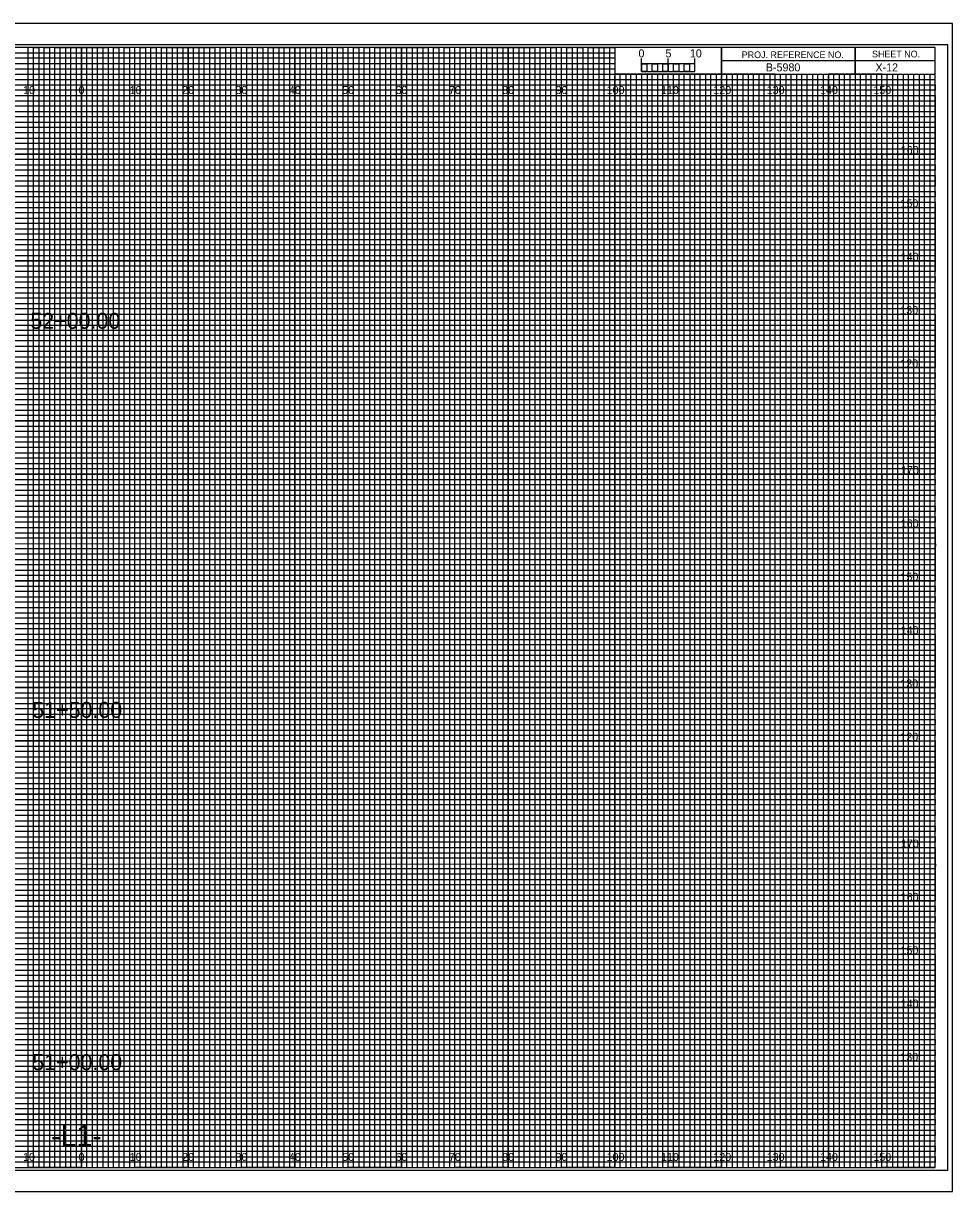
# Model space of a CAD drawing. Extents: x -13 to 323, y -5 to 3294.
# Drawn here: x 149.1 to 323.3, y 2415.5 to 2634.5 of the extents above; entities that cross this region are included whole.
import ezdxf

# ---------------------------------------------------------------- set-up
doc = ezdxf.new("R2010")
doc.units = 0
for name, color, linetype in [('Prop XS Alignment Label', 7, 'Continuous'), ('Prop XS Bar Scale Labels', 7, 'Continuous'), ('Prop XS Elevation Labels', 7, 'Continuous'), ('Prop XS Offset Labels', 7, 'Continuous'), ('Prop XS Project Number', 7, 'Continuous'), ('Prop XS Sheet Number', 7, 'Continuous'), ('Prop XS Station Labels', 7, 'Continuous'), ('Scratch_Level_0', 7, 'Continuous'), ('Sheet Cross Section CELL', 7, 'Continuous'), ('Sheet Cross Section Grid Major CELL', 7, 'Continuous'), ('Sheet Cross Section Grid Middle CELL', 7, 'Continuous'), ('Sheet Cross Section Grid Minor 1 CELL', 7, 'Continuous'), ('Sheet Cross Section Grid Minor 2 CELL', 7, 'Continuous'), ('Sheet Cross Section Scale CELL', 7, 'Continuous'), ('Sheet Cutting Line CELL', 7, 'Continuous'), ('Sheet DOT Grid CELL', 7, 'Continuous'), ('Sheet Plot Border Inside CELL', 7, 'Continuous'), ('Sheet Plot Border Outside CELL', 7, 'Continuous')]:
    doc.layers.add(name, color=color, linetype=linetype)

msp = doc.modelspace()

# ---------------------------------------------------------------- linework, layer by layer
at = {"layer": 'Scratch_Level_0'}
for points in [[(10, 2610), (310, 2610), (310, 2560), (10, 2560)], [(5, 2550), (310, 2550), (310, 2500), (5, 2500)], [(10, 2480), (310, 2480), (310, 2430), (10, 2430)]]:
    msp.add_lwpolyline(points, close=True, dxfattribs=at)
at = {"layer": 'Sheet Cross Section CELL'}
for p, q in [((305, 2630), (305, 2625)), ((305, 2625), (305, 2630)), ((280, 2627.5), (280, 2625)), ((320, 2627.49), (280, 2627.49)), ((280, 2625), (320, 2625))]:
    msp.add_line(p, q, dxfattribs=at)
for points in [[(320, 2630), (0, 2630), (0, 2420), (320, 2420)], [(280, 2630), (260, 2630), (260, 2625.03), (280, 2625.03)], [(320, 2630), (280, 2630), (280, 2625), (320, 2625)]]:
    msp.add_lwpolyline(points, close=True, dxfattribs=at)
at = {"layer": 'Sheet Cross Section Grid Major CELL'}
for p, q in [((150, 2630), (140, 2630)), ((150, 2420), (150, 2630)), ((170, 2630), (160, 2630)), ((160, 2630), (160, 2420)), ((170, 2420), (170, 2630)), ((190, 2630), (180, 2630)), ((180, 2630), (180, 2420)), ((190, 2420), (190, 2630)), ((210, 2630), (200, 2630)), ((200, 2630), (200, 2420)), ((210, 2420), (210, 2630)), ((230, 2630), (220, 2630)), ((220, 2630), (220, 2420)), ((230, 2420), (230, 2630)), ((250, 2630), (240, 2630)), ((240, 2630), (240, 2420)), ((250, 2420), (250, 2630)), ((260, 2630), (260, 2420)), ((270, 2420), (270, 2625)), ((290, 2625), (280, 2625)), ((280, 2625), (280, 2420)), ((290, 2420), (290, 2625)), ((310, 2625), (300, 2625)), ((300, 2625), (300, 2420)), ((310, 2420), (310, 2625)), ((160, 2420), (150, 2420)), ((180, 2420), (170, 2420)), ((200, 2420), (190, 2420)), ((220, 2420), (210, 2420)), ((240, 2420), (230, 2420)), ((260, 2420), (250, 2420)), ((280, 2420), (270, 2420)), ((300, 2420), (290, 2420)), ((320, 2420), (310, 2420)), ((320, 2420), (320, 2420))]:
    msp.add_line(p, q, dxfattribs=at)
for points in [[(0, 2620), (320, 2620), (320, 2610), (0, 2610)], [(0, 2600), (320, 2600), (320, 2590), (0, 2590)], [(0, 2580), (320, 2580), (320, 2570), (0, 2570)], [(0, 2560), (320, 2560), (320, 2550), (0, 2550)], [(0, 2540), (320, 2540), (320, 2530), (0, 2530)], [(0, 2520), (320, 2520), (320, 2510), (0, 2510)], [(0, 2500), (320, 2500), (320, 2490), (0, 2490)], [(0, 2480), (320, 2480), (320, 2470), (0, 2470)], [(0, 2460), (320, 2460), (320, 2450), (0, 2450)], [(0, 2440), (320, 2440), (320, 2430), (0, 2430)]]:
    msp.add_lwpolyline(points, dxfattribs=at)
at = {"layer": 'Sheet Cross Section Grid Middle CELL'}
for points in [[(145, 2420), (155, 2420), (155, 2630), (165, 2630), (165, 2420), (175, 2420), (175, 2630), (185, 2630), (185, 2420), (195, 2420), (195, 2630), (205, 2630), (205, 2420), (215, 2420), (215, 2630), (225, 2630), (225, 2420), (235, 2420), (235, 2630), (245, 2630), (245, 2420), (255, 2420), (255, 2630), (259.93, 2630), (260, 2630), (260, 2625), (264.99, 2625), (264.99, 2420), (275, 2420), (275, 2625), (285, 2625), (285, 2420), (295, 2420), (295, 2625), (305, 2625), (305, 2420), (315, 2420), (315, 2625)], [(0, 2625), (275, 2625)], [(0, 2605), (320, 2605), (320, 2615), (0, 2615)], [(0, 2585), (320, 2585), (320, 2595), (0, 2595)], [(0, 2565), (320, 2565), (320, 2575), (0, 2575)], [(0, 2545), (320, 2545), (320, 2555), (0, 2555)], [(0, 2525), (320, 2525), (320, 2535), (0, 2535)], [(0, 2505), (320, 2505), (320, 2515), (0, 2515)], [(0, 2485), (320, 2485), (320, 2495), (0, 2495)], [(0, 2465), (320, 2465), (320, 2475), (0, 2475)], [(0, 2445), (320, 2445), (320, 2455), (0, 2455)], [(0, 2425), (320, 2425), (320, 2435), (0, 2435)]]:
    msp.add_lwpolyline(points, dxfattribs=at)
at = {"layer": 'Sheet Cross Section Grid Minor 1 CELL'}
for p, q in [((0, 2629), (260, 2629)), ((260, 2629), (260, 2627.98)), ((260, 2627.98), (0, 2627.98)), ((0, 2627), (260, 2627)), ((260, 2625.89), (0, 2625.89)), ((260, 2627), (260, 2625.89)), ((0, 2624), (320, 2624))]:
    msp.add_line(p, q, dxfattribs=at)
for points in [[(0, 2623), (270, 2623), (320, 2623), (320, 2622), (0, 2622)], [(0, 2621), (320, 2621), (320, 2619), (0, 2619)], [(0, 2618), (320, 2618), (320, 2617), (0, 2616.98)], [(0, 2616), (320, 2616), (320, 2614), (0, 2614)], [(0, 2613), (320, 2613), (320, 2612), (0, 2612)], [(0, 2611), (320, 2611), (320, 2609), (0, 2609)], [(0, 2608), (320, 2608), (320, 2607), (0, 2607)], [(0, 2606), (320, 2606), (320, 2604), (0, 2604)], [(0, 2603), (320, 2603), (320, 2602), (0, 2602)], [(0, 2601), (320, 2601), (320, 2599), (0, 2599)], [(0, 2598), (320, 2598), (320, 2597), (0, 2597)], [(0, 2596), (320, 2596), (320, 2593.95), (320, 2593), (320, 2592), (0, 2592)], [(0, 2594), (320, 2594), (320, 2593), (0, 2593)], [(0, 2591), (320, 2591), (320, 2589), (0, 2589.03)], [(0, 2589.03), (320, 2589), (320, 2588), (0, 2588)], [(0, 2587), (320, 2587), (320, 2586), (0, 2586)], [(0, 2584), (320, 2584), (320, 2583), (0, 2583)], [(0, 2582), (320, 2582), (320, 2581), (0, 2581)], [(-0.07, 2578.89), (320, 2578.89), (320, 2577.88), (-0.07, 2577.88)], [(0, 2577), (320, 2577), (320, 2576), (0, 2576)], [(0, 2574), (320, 2574), (320, 2573), (0, 2573)], [(0, 2572), (320, 2572), (320, 2571), (0, 2571)], [(0, 2569), (320, 2569), (320, 2568), (0, 2568)], [(0, 2567), (320, 2567), (320, 2566), (0, 2566)], [(0, 2564), (320, 2564), (320, 2563), (0, 2563)], [(0, 2562), (320, 2562), (320, 2561), (0, 2561)], [(0, 2559), (320, 2559), (319.99, 2557.98), (0, 2558)], [(0, 2557), (320, 2557), (320, 2556), (0, 2556)], [(0, 2554), (320, 2554), (320, 2553), (0, 2553)], [(0, 2552), (320, 2552), (320, 2551), (0, 2551)], [(0, 2549), (320, 2549), (320, 2548), (0, 2548)], [(0, 2547), (320, 2547), (320, 2546), (0, 2546)], [(0, 2544), (320, 2544), (320, 2543), (0, 2543)], [(0, 2542), (320, 2542), (320, 2541), (0, 2541)], [(0, 2539), (320, 2539), (320, 2538), (0, 2538)], [(0, 2536.99), (320.07, 2536.91), (320, 2536), (0, 2536)], [(0, 2534), (320, 2534), (320, 2533), (0, 2533)], [(0, 2532), (320, 2532), (320, 2531), (0, 2531)], [(0, 2529), (320, 2529), (320, 2528), (0, 2528)], [(0, 2527), (320, 2527), (320, 2526), (0, 2526)], [(0, 2524), (320, 2524), (320, 2523), (0, 2523)], [(0, 2522), (320, 2522), (320, 2521), (0, 2521)], [(0, 2519), (320, 2519), (320, 2518), (0, 2518)], [(0, 2517), (320, 2517), (320, 2516), (0, 2516)], [(0, 2514), (320, 2514), (320, 2513), (0, 2513)], [(0, 2512), (320, 2512), (320, 2511), (0, 2511)], [(0, 2509), (320, 2509), (320, 2508), (0, 2508)], [(0, 2507), (320, 2507), (320, 2506), (0, 2506)], [(0, 2504), (320, 2504), (320, 2503), (0, 2503)], [(0, 2502), (320, 2502), (320, 2501), (0, 2501)], [(0, 2499), (320, 2499), (319.99, 2497.98), (0, 2498)], [(0, 2497), (320, 2497), (320, 2496), (0, 2496)], [(0, 2494), (320, 2494), (320, 2493), (0, 2493)], [(0, 2492), (320, 2492), (320, 2491), (0, 2491)], [(0, 2489), (320, 2489), (320, 2488), (0, 2488)], [(0, 2487), (320, 2487), (320, 2486), (0, 2486)], [(0, 2484), (320, 2484), (320, 2483), (0, 2483)], [(0, 2482), (320, 2482), (320, 2481), (0, 2481)], [(0, 2479), (320, 2479), (320, 2478), (0, 2478)], [(0, 2476.99), (320.07, 2476.91), (320, 2476), (0, 2476)], [(0, 2474), (320, 2474), (320, 2473), (0, 2473)], [(0, 2472), (320, 2472), (320, 2471), (0, 2471)], [(0, 2469), (320, 2469), (320, 2468), (0, 2468)], [(0, 2467), (320, 2467), (320, 2466), (0, 2466)], [(0, 2464), (320, 2464), (320, 2463), (0, 2463)], [(0, 2462), (320, 2462), (320, 2461), (0, 2461)], [(0, 2459), (320, 2459), (320, 2458), (0, 2458)], [(0, 2457), (320, 2457), (320, 2456), (0, 2456)], [(0, 2454), (320, 2454), (320, 2453), (0, 2453)], [(0, 2452), (320, 2452), (320, 2451), (0, 2451)], [(0, 2449), (320, 2449), (320, 2448), (0, 2448)], [(0, 2447), (320, 2447), (320, 2446), (0, 2446)], [(0, 2444), (320, 2444), (320, 2443), (0, 2443)], [(0, 2442), (320, 2442), (320, 2441), (0, 2441)], [(0, 2439), (320, 2439), (320, 2438), (0, 2438)], [(0, 2437), (320, 2437), (320, 2436), (0, 2436)], [(0, 2434), (320, 2434), (320, 2433), (0, 2433)], [(0, 2432), (320, 2432), (320, 2431), (0, 2431)], [(0, 2429), (320, 2429), (320, 2428), (0, 2428)], [(0, 2427), (320, 2427), (320, 2426), (0, 2426)], [(0, 2424), (320, 2424), (320, 2423), (0, 2423)], [(0, 2422), (320, 2422), (320, 2421), (0, 2421)]]:
    msp.add_lwpolyline(points, dxfattribs=at)
at = {"layer": 'Sheet Cross Section Grid Minor 2 CELL'}
for p, q in [((267, 2625), (266.01, 2625)), ((266.01, 2625), (266.01, 2420)), ((267, 2420), (267, 2625)), ((269, 2625), (268, 2625)), ((268, 2625), (268, 2420)), ((269, 2420), (269, 2625)), ((266.01, 2420), (265, 2420)), ((268, 2420), (267, 2420))]:
    msp.add_line(p, q, dxfattribs=at)
for points in [[(150, 2420), (151, 2420), (151, 2630), (152, 2630), (152, 2420)], [(152, 2420), (153, 2420), (153, 2630), (154, 2630), (154, 2420)], [(155, 2420), (156, 2420), (156, 2630), (157, 2630), (157, 2420)], [(157, 2420), (158, 2420), (158, 2630), (159, 2630), (159, 2420)], [(160, 2420), (161, 2420), (161, 2630), (162, 2630), (162, 2420)], [(162, 2420), (163, 2420), (163, 2630), (164, 2630), (164, 2420)], [(165, 2420), (166, 2420), (166, 2630), (167, 2630), (167, 2420)], [(167, 2420), (168, 2420), (168, 2630), (169, 2630), (169, 2420)], [(170, 2420), (171, 2420), (171, 2630), (172, 2630), (172, 2420)], [(172, 2420), (173, 2420), (173, 2630), (174, 2630), (174, 2420)], [(175, 2420), (176, 2420), (176, 2630), (177, 2630), (177, 2420)], [(177, 2420), (178, 2420), (178, 2630), (179, 2630), (179, 2420)], [(180, 2420), (181, 2420), (181, 2630), (182, 2630), (182, 2420)], [(182, 2420), (183, 2420), (183, 2630), (184, 2630), (184, 2420)], [(185, 2420), (186, 2420), (186, 2630), (187, 2630), (187, 2420)], [(187, 2420), (188, 2420), (188, 2630), (189, 2630), (189, 2420)], [(190, 2420), (191, 2420), (191, 2630), (192, 2630), (192, 2420)], [(192, 2420), (193, 2420), (193, 2630), (194, 2630), (194, 2420)], [(195, 2420), (196, 2420), (196, 2630), (197, 2630), (197, 2420)], [(197, 2420), (198, 2420), (198, 2630), (199, 2630), (199, 2420)], [(200, 2420), (201, 2420), (201, 2630), (202, 2630), (202, 2420)], [(202, 2420), (203, 2420), (203, 2630), (204, 2630), (204, 2420)], [(205, 2420), (206, 2420), (206, 2630), (207, 2630), (207, 2420)], [(207, 2420), (208, 2420), (208, 2630), (209, 2630), (209, 2420)], [(210, 2420), (211, 2420), (211, 2630), (212, 2630), (212, 2420)], [(212, 2420), (213, 2420), (213, 2630), (214, 2630), (214, 2420)], [(215, 2420), (216, 2420), (216, 2630), (217, 2630), (217, 2420)], [(217, 2420), (218, 2420), (218, 2630), (219, 2630), (219, 2420)], [(220, 2420), (221, 2420), (221, 2630), (222, 2630), (222, 2420)], [(222, 2420), (223, 2420), (223, 2630), (224, 2630), (224, 2420)], [(225, 2420), (226, 2420), (226, 2630), (227, 2630), (227, 2420)], [(227, 2420), (228, 2420), (228, 2630), (229, 2630), (229, 2420)], [(230, 2420), (231, 2420), (231, 2630), (232, 2630), (232, 2420)], [(232, 2420), (233, 2420), (233, 2630), (234, 2630), (234, 2420)], [(235, 2420), (236, 2420), (236, 2630), (237, 2630), (237, 2420)], [(237, 2420), (238, 2420), (238, 2630), (239, 2630), (239, 2420)], [(240, 2420), (241, 2420), (241, 2630), (242, 2630), (242, 2420)], [(242, 2420), (243, 2420), (243, 2630), (244, 2630), (244, 2420)], [(245, 2420), (246, 2420), (246, 2630), (247, 2630), (247, 2420)], [(247, 2420), (248, 2420), (248, 2630), (249, 2630), (249, 2420)], [(250, 2420), (251, 2420), (251, 2630), (252, 2630), (252, 2420)], [(252, 2420), (253, 2420), (253, 2630), (254, 2630), (254, 2420)], [(255, 2420), (256, 2420), (256, 2630), (257, 2630), (257, 2420)], [(257, 2420), (258, 2420), (258, 2630), (259, 2630), (259, 2420)], [(260, 2420), (261, 2420), (261, 2625), (262.02, 2625), (262.02, 2420)], [(262, 2420), (263, 2420), (263, 2625), (263.99, 2625), (263.99, 2420)], [(270, 2420), (270.98, 2420), (270.98, 2625), (272, 2625), (272, 2420)], [(272, 2420), (273, 2420), (273, 2625), (274.05, 2625), (274.05, 2420)], [(275, 2420), (276, 2420), (276, 2625), (277, 2625), (277, 2420)], [(277, 2420), (278, 2420), (278, 2625), (279, 2625), (279, 2420)], [(280, 2420), (281, 2420), (281, 2625), (282, 2625), (282, 2420)], [(282, 2420), (283, 2420), (283, 2625), (284, 2625), (284, 2420)], [(285, 2420), (286, 2420), (286, 2625), (287, 2625), (287, 2420)], [(287, 2420), (288, 2420), (288, 2625), (289, 2625), (289, 2420)], [(290, 2420), (291, 2420), (291, 2625), (292, 2625), (292, 2420)], [(292, 2420), (293, 2420), (293, 2625), (294, 2625), (294, 2420)], [(295, 2420), (296, 2420), (296, 2625), (297, 2625), (297, 2420)], [(297, 2420), (298, 2420), (298, 2625), (299, 2625), (299, 2420)], [(300, 2420), (301, 2420), (301, 2625), (302, 2625), (302, 2420)], [(302, 2420), (303, 2420), (303, 2625), (304, 2625), (304, 2420)], [(305, 2420), (306, 2420), (306, 2625), (307, 2625), (307, 2420)], [(307, 2420), (308, 2420), (308, 2625), (309, 2625), (309, 2420)], [(310, 2420), (311, 2420), (311, 2625), (312, 2625), (312, 2420)], [(312, 2420), (313, 2420), (313, 2625), (314, 2625), (314, 2420)], [(315, 2420), (316, 2420), (316, 2625), (317, 2625), (317, 2420)], [(317, 2420), (318, 2420), (318, 2625), (319, 2625), (319, 2420)]]:
    msp.add_lwpolyline(points, dxfattribs=at)
at = {"layer": 'Sheet Cross Section Scale CELL'}
for p, q in [((265, 2625.49), (265, 2627.9)), ((265, 2626.9), (265, 2627.9)), ((270, 2625.49), (270, 2627.9)), ((275, 2625.49), (275, 2627.9)), ((275, 2626.9), (275, 2627.9))]:
    msp.add_line(p, q, dxfattribs=at)
for points in [[(275, 2626.9), (265, 2626.9), (265, 2625.49), (275, 2625.49)], [(265, 2626.9), (266, 2626.9), (266, 2625.49), (265, 2625.49)], [(267, 2626.9), (268, 2626.9), (268, 2625.49), (267, 2625.49)], [(269, 2626.9), (270, 2626.9), (270, 2625.49), (269, 2625.49)], [(271, 2626.9), (272, 2626.9), (272, 2625.49), (271, 2625.49)], [(273, 2626.9), (274, 2626.9), (274, 2625.49), (273, 2625.49)]]:
    msp.add_lwpolyline(points, close=True, dxfattribs=at)
at = {"layer": 'Sheet Cutting Line CELL'}
for p, q in [((323.3, 2634.5), (-13.4, 2634.5)), ((-13.4, 2415.5), (323.3, 2415.5))]:
    msp.add_line(p, q, dxfattribs=at)
at = {"layer": 'Sheet DOT Grid CELL'}
for p, q in [((150, 2420), (150, 2630)), ((160, 2420), (160, 2630)), ((170, 2420), (170, 2630)), ((180, 2420), (180, 2630)), ((190, 2420), (190, 2630)), ((200, 2420), (200, 2630)), ((210, 2420), (210, 2630)), ((220, 2420), (220, 2630)), ((230, 2420), (230, 2630)), ((240, 2420), (240, 2630)), ((250, 2420), (250, 2630)), ((260, 2420), (260, 2624.69)), ((270, 2420), (270, 2624.69)), ((280, 2420), (280, 2624.69)), ((290, 2420), (290, 2624.69)), ((300, 2420), (300, 2624.69)), ((310, 2420), (310, 2624.69)), ((0, 2620), (320, 2620)), ((0, 2610), (320, 2610)), ((0, 2600), (320, 2600)), ((0, 2590), (320, 2590)), ((0, 2580), (320, 2580)), ((0, 2570), (320, 2570)), ((0, 2560), (320, 2560)), ((0, 2550), (320, 2550)), ((0, 2540), (320, 2540)), ((0, 2530), (320, 2530)), ((0, 2520), (320, 2520)), ((0, 2510), (320, 2510)), ((0, 2500), (320, 2500)), ((0, 2490), (320, 2490)), ((0, 2480), (320, 2480)), ((0, 2470), (320, 2470)), ((0, 2460), (320, 2460)), ((0, 2450), (320, 2450)), ((0, 2440), (320, 2440)), ((0, 2430), (320, 2430))]:
    msp.add_line(p, q, dxfattribs=at)
at = {"layer": 'Sheet Plot Border Inside CELL'}
msp.add_lwpolyline([(-10.8, 2419.5), (322.4, 2419.5), (322.4, 2630.5), (-10.8, 2630.5)], close=True, dxfattribs=at)
at = {"layer": 'Sheet Plot Border Outside CELL'}
msp.add_lwpolyline([(-13.4, 2415.5), (323.3, 2415.5), (323.3, 2634.5), (-13.4, 2634.5)], close=True, dxfattribs=at)

# ---------------------------------------------------------------- texts
at = {"layer": 'Prop XS Alignment Label'}
msp.add_text('-L1-', height=4, dxfattribs=at).set_placement((154.28, 2424))
at = {"layer": 'Prop XS Bar Scale Labels'}
for s, p in [('5', (269.47, 2628.12)), ('10', (274.04, 2628.12))]:
    msp.add_text(s, height=1.5, dxfattribs=at).set_placement(p)
at = {"layer": 'Prop XS Elevation Labels'}
for s, p in [('160', (313.57, 2610)), ('150', (313.52, 2600)), ('140', (313.57, 2590)), ('130', (313.49, 2580)), ('120', (313.5, 2570)), ('170', (313.61, 2550)), ('160', (313.57, 2540)), ('150', (313.52, 2530)), ('140', (313.57, 2520)), ('130', (313.49, 2510)), ('120', (313.5, 2500)), ('170', (313.61, 2480)), ('160', (313.57, 2470)), ('150', (313.52, 2460)), ('140', (313.57, 2450)), ('130', (313.49, 2440))]:
    msp.add_text(s, height=1.5, dxfattribs=at).set_placement(p)
at = {"layer": 'Prop XS Offset Labels'}
for s, p in [('10', (149.04, 2621.25)), ('0', (159.45, 2621.25)), ('0', (159.45, 2621.25)), ('10', (169.04, 2621.25)), ('20', (178.86, 2621.25)), ('30', (188.86, 2621.25)), ('40', (198.86, 2621.25)), ('50', (208.86, 2621.25)), ('60', (218.86, 2621.25)), ('70', (228.86, 2621.25)), ('80', (238.86, 2621.25)), ('90', (248.86, 2621.25)), ('100', (258.44, 2621.25)), ('110', (268.62, 2621.25)), ('120', (278.44, 2621.25)), ('130', (288.44, 2621.25)), ('140', (298.44, 2621.25)), ('150', (308.44, 2621.25)), ('10', (149.04, 2421.25)), ('0', (159.45, 2421.25)), ('0', (159.45, 2421.25)), ('10', (169.04, 2421.25)), ('20', (178.86, 2421.25)), ('30', (188.86, 2421.25)), ('40', (198.86, 2421.25)), ('50', (208.86, 2421.25)), ('60', (218.86, 2421.25)), ('70', (228.86, 2421.25)), ('80', (238.86, 2421.25)), ('90', (248.86, 2421.25)), ('100', (258.44, 2421.25)), ('110', (268.62, 2421.25)), ('120', (278.44, 2421.25)), ('130', (288.44, 2421.25)), ('140', (298.44, 2421.25)), ('150', (308.44, 2421.25))]:
    msp.add_text(s, height=1.5, dxfattribs=at).set_placement(p)
at = {"layer": 'Prop XS Project Number'}
msp.add_text('B-5980', height=1.5, dxfattribs=at).set_placement((288.28, 2625.5))
at = {"layer": 'Prop XS Sheet Number'}
msp.add_text('X-12', height=1.5, dxfattribs=at).set_placement((308.83, 2625.5))
at = {"layer": 'Prop XS Station Labels'}
for s, p in [('52+00.00', (150.41, 2577.25)), ('51+50.00', (150.77, 2504.31)), ('51+00.00', (150.77, 2438.27))]:
    msp.add_text(s, height=3, dxfattribs=at).set_placement(p)
at = {"layer": 'Sheet Cross Section CELL'}
for s, p in [('PROJ. REFERENCE NO.', (283.77, 2627.99)), ('SHEET NO.', (308.19, 2628.12))]:
    msp.add_text(s, height=1.25, dxfattribs=at).set_placement(p)
at = {"layer": 'Sheet Cross Section Scale CELL'}
msp.add_text('0', height=1.5, dxfattribs=at).set_placement((264.41, 2628.12))

doc.saveas('drawing.dxf')
